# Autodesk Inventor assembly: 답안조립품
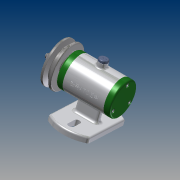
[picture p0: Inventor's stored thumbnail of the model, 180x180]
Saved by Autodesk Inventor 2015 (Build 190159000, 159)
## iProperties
Created: 2017-12
Part Number: 답안조립품
Document SubType Name: Assembly
Designer: 2-PC06
Author: 2-PC06
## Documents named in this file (14)
- C:\Users\2-PC06\Desktop\471207V1001\답안조립품.iam
- C:\Users\2-PC06\Desktop\471207V1001\본체.ipt
- C:\Users\2-PC06\Desktop\471207V1001\V벨트풀리.ipt
- C:\Users\2-PC06\Desktop\471207V1001\고무캡.ipt
- C:\Users\2-PC06\Desktop\471207V1001\너트 M 8.ipt
- C:\Users\2-PC06\Desktop\471207V1001\뒤커버.ipt
- C:\Users\2-PC06\Desktop\471207V1001\베어링 15 x 32 x 9.ipt
- C:\Users\2-PC06\Desktop\471207V1001\볼트 M4 x 12.ipt
- C:\Users\2-PC06\Desktop\471207V1001\스프링와셔 8.ipt
- C:\Users\2-PC06\Desktop\471207V1001\앞커버.ipt
- C:\Users\2-PC06\Desktop\471207V1001\오일 실 15 25 7.ipt
- C:\Users\2-PC06\Desktop\471207V1001\와셔 8x17.ipt
- C:\Users\2-PC06\Desktop\471207V1001\축.ipt
- C:\Users\2-PC06\Desktop\471207V1001\키 3 x 3 x 12.ipt
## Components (2 placed, 2 different names)
1. V벨트풀리:1 — 각도:2
2. 고무캡:1 — 각도:3
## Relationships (2: Angle 2)
- 각도:2 [Angle]: V벨트풀리:1
- 각도:3 [Angle]: 고무캡:1
